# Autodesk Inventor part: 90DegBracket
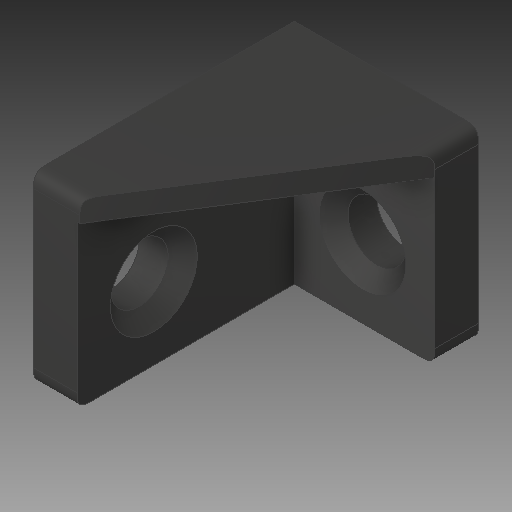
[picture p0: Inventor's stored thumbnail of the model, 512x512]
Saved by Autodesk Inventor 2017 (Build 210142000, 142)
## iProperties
Created: 2017-05
Part Number: 90DegBracket
Material: Generic
Document SubType Name: Modeling
Designer: Savy
Density: 1 g/cm^3
Appearance: Default
Mass: 1.07528 g
Surface Area: 10.9272 cm^2
Volume: 1.07528 cm^3
Author: Savy
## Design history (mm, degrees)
feature "Base1"
body "Solid1"
